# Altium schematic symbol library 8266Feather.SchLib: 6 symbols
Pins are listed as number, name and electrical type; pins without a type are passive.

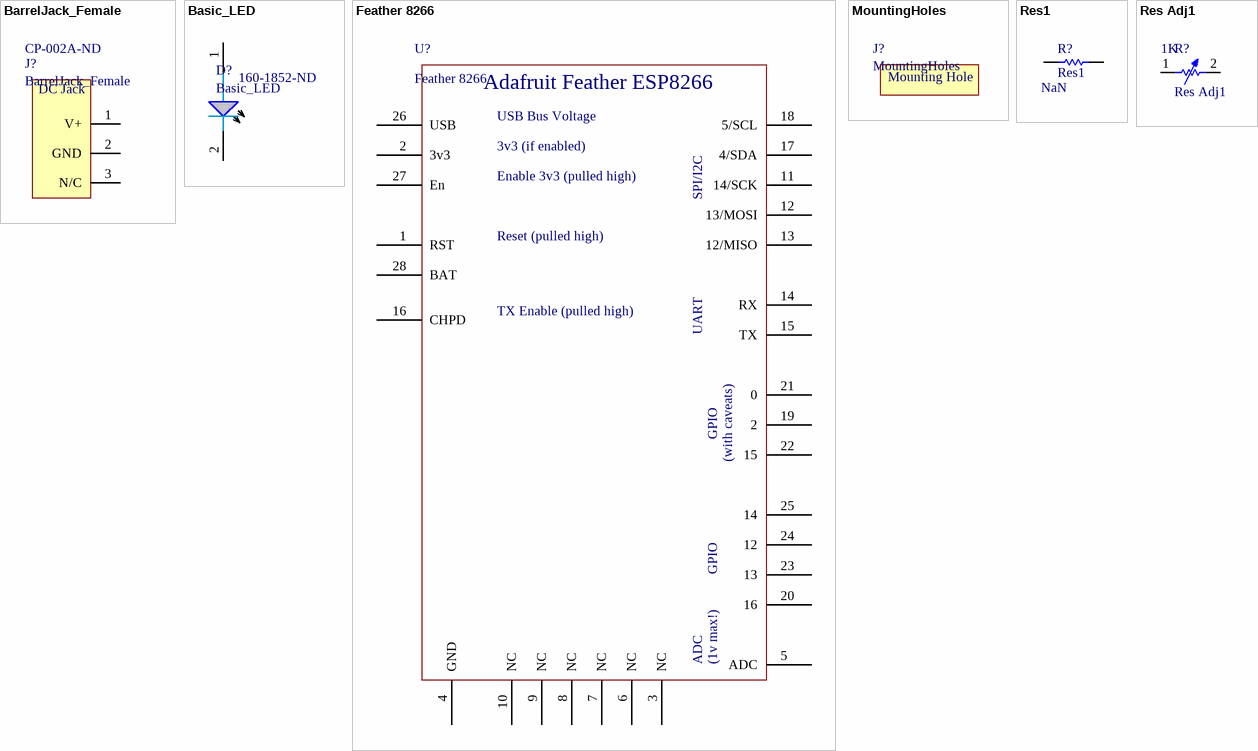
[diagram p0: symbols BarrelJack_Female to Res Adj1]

## BarrelJack_Female
designator J?  Supplier Part Number 1: CP-002A-ND
Manufacturer: CUI Inc; Manufacturer Part Number: PJ-002A; Connector Type: Jack; Gender: Male; Plug/Mating Plug Diameter: 2.1mm ID, 5.5mm OD; Number of Positions/Contacts: 2 Conductors, 3 Contacts; Internal Switch(s): Single Switch, Normally Closed; Shielding: Unshielded; Voltage - Rated: 16VDC; Current Rating: 2.5A
footprint BarrelJack (Basic DC Barrel Jack)
pins: 1 V+ (power), 2 GND (power), 3 N/C

## Basic_LED
designator D?  Supplier Part Number 1: 160-1852-ND
Manufacturer: Lite-On Inc.; Manufacturer Part Number: LTL2R3KGD-EM; Color: Green; Lens Transparency: Diffused; Millicandela Rating: 38mcd; Lens Style/Size: Round with Domed Top, 5.00mm; Voltage - Forward (Vf) (Typ): 1.8V; Current - Test: 2mA; Viewing Angle: 30°; Wavelength - Dominant: 570nm; Wavelength - Peak: 568nm
footprint Basic_LED - Through hole
pins: 1 0, 2

## Feather 8266
designator U?
footprint Adafruit Feather 8266
pins: 1 RST, 2 3v3, 3 NC, 4 GND, 5 ADC, 6 NC, 7 NC, 8 NC, 9 NC, 10 NC, 11 14/SCK, 12 13/MOSI, 13 12/MISO, 14 RX, 15 TX, 16 CHPD, 17 4/SDA, 18 5/SCL, 19 2, 20 16, 21 0, 22 15, 23 13, 24 12, 25 14, 26 USB, 27 En, 28 BAT

## MountingHoles
designator J?
footprint Mounting Hole - Single

## Res1
designator R?  Resistance (Ohms): NaN
Resistor; Value: 1K
footprint AXIAL-0.3 (Axial Device, Thru-Hole; 2 Leads; 0.3 in Pin Spacing)
pins: 1, 2

## Res Adj1
designator R?  value 1K
Variable Resistor
footprint LOG POT
pins: 1, 2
